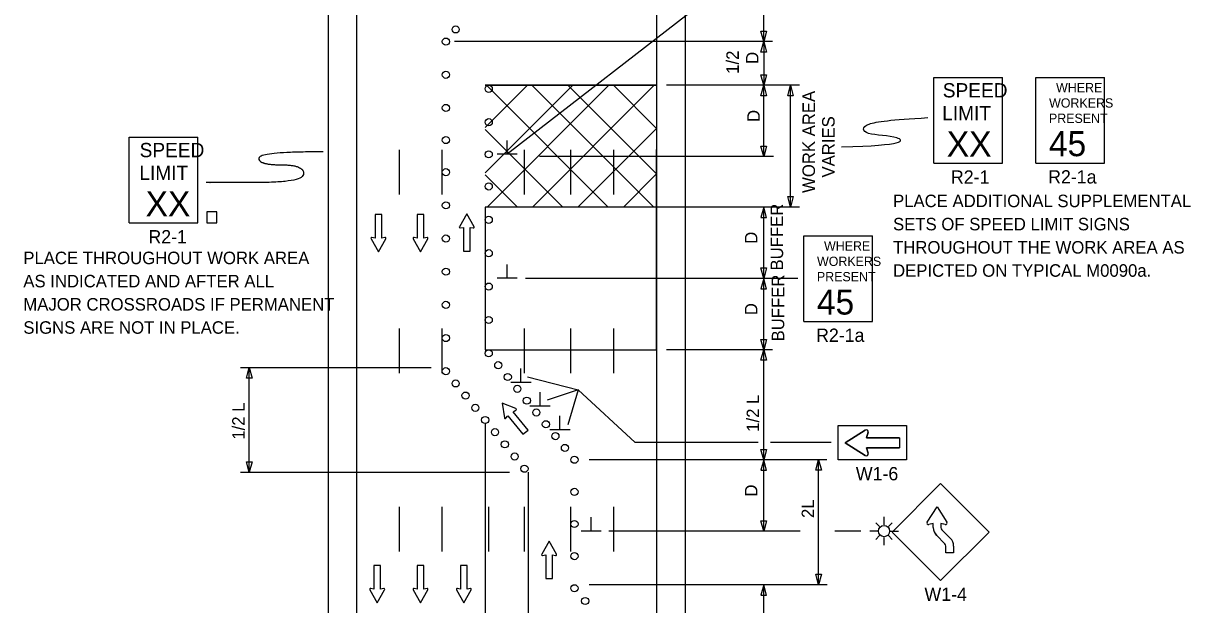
# Model space of a CAD drawing. Extents: x 16038 to 19504, y 5710 to 8321.
# Drawn here: x 16768 to 17422, y 6199 to 6525 of the extents above; entities that cross this region are included whole.
import ezdxf

# ---------------------------------------------------------------- set-up
doc = ezdxf.new("R2010")
doc.units = 0
for name, color, linetype in [('ALI_LEGAL_EX', 7, 'Continuous'), ('Level 3', 7, 'Continuous'), ('MT_SCRATCH_LEVEL_A', 7, 'Continuous'), ('MT_SCRATCH_LEVEL_E', 7, 'Continuous'), ('PAVT_EDGE_EX', 7, 'Continuous'), ('TRAFFIC_SIGNS_PR', 7, 'Continuous'), ('TYPICAL_EX', 7, 'Continuous'), ('TYPICAL_TEXT_DIMEN_PR', 7, 'Continuous')]:
    doc.layers.add(name, color=color, linetype=linetype)

msp = doc.modelspace()

# ---------------------------------------------------------------- linework, layer by layer
at = {"layer": 'ALI_LEGAL_EX'}
for points in [[(16978.71, 6429.12), (16978.71, 6454.12)], [(17002.71, 6429.12), (17002.71, 6454.12)], [(17048.71, 6429.12), (17048.71, 6454.12)], [(17074.71, 6429.12), (17074.71, 6454.12)], [(17098.71, 6429.12), (17098.71, 6454.12)], [(16978.71, 6329.12), (16978.71, 6354.12)], [(17002.71, 6329.12), (17002.71, 6354.12)], [(17048.71, 6329.12), (17048.71, 6354.12)], [(17074.71, 6329.12), (17074.71, 6354.12)], [(17098.71, 6329.12), (17098.71, 6354.12)], [(16978.71, 6229.12), (16978.71, 6254.12)], [(17002.71, 6229.12), (17002.71, 6254.12)], [(17028.71, 6229.12), (17028.71, 6254.12)], [(17048.71, 6229.12), (17048.71, 6254.12)], [(17074.71, 6229.12), (17074.71, 6254.12)], [(17098.71, 6229.12), (17098.71, 6254.12)]]:
    msp.add_lwpolyline(points, dxfattribs=at)
at = {"layer": 'Level 3'}
for p, q in [((17188.13, 6450.36), (17057.15, 6450.36)), ((17202.83, 6422.13), (17026.71, 6422.13)), ((17201.76, 6382.13), (17049.31, 6382.13)), ((17203.18, 6240.46), (17095.93, 6240.46)), ((17237.06, 6240.46), (17222.58, 6240.46))]:
    msp.add_line(p, q, dxfattribs=at)
at = {"layer": 'MT_SCRATCH_LEVEL_A'}
for p, q in [((17026.71, 6490.36), (17122.71, 6490.36)), ((17122.71, 6490.36), (17026.71, 6490.36)), ((17026.71, 6466.73), (17050.34, 6490.36)), ((17026.71, 6441.27), (17075.8, 6490.36)), ((17095.68, 6422.13), (17027.45, 6490.36)), ((17027.74, 6422.13), (17095.97, 6490.36)), ((17121.14, 6422.13), (17052.91, 6490.36)), ((17053.19, 6422.13), (17121.43, 6490.36)), ((17122.71, 6440.73), (17073.08, 6490.36)), ((17122.71, 6466.19), (17098.53, 6490.36)), ((17070.23, 6422.13), (17026.71, 6465.64)), ((17078.65, 6422.13), (17122.71, 6466.19)), ((17122.71, 6454.36), (17122.71, 6342.13)), ((17122.71, 6454.36), (17122.71, 6342.13)), ((17122.71, 6370.19), (17122.71, 6454.36)), ((17044.77, 6422.13), (17026.71, 6440.19)), ((17104.11, 6422.13), (17122.71, 6440.73)), ((17026.71, 6342.13), (17122.71, 6342.13)), ((17026.71, 6342.13), (17122.71, 6342.13))]:
    msp.add_line(p, q, dxfattribs=at)
at = {"layer": 'MT_SCRATCH_LEVEL_E'}
for p, q in [((16968.81, 6417.97), (16965.07, 6417.97)), ((16965.07, 6417.97), (16965.07, 6404.71)), ((16968.81, 6417.97), (16965.07, 6417.97)), ((16965.07, 6417.97), (16965.07, 6404.71)), ((16968.81, 6404.71), (16968.81, 6417.97)), ((16968.81, 6404.71), (16968.81, 6417.97)), ((16992.38, 6417.97), (16988.64, 6417.97)), ((16988.64, 6417.97), (16988.64, 6404.71)), ((16992.38, 6417.97), (16988.64, 6417.97)), ((16988.64, 6417.97), (16988.64, 6404.71)), ((16992.38, 6404.71), (16992.38, 6417.97)), ((16992.38, 6404.71), (16992.38, 6417.97)), ((17016.39, 6418.35), (17012.28, 6411.11)), ((17016.39, 6418.35), (17012.28, 6411.11)), ((17016.39, 6418.35), (17012.28, 6411.11)), ((17016.39, 6418.35), (17012.28, 6411.11)), ((17020.54, 6411.11), (17016.39, 6418.35)), ((17020.54, 6411.11), (17016.39, 6418.35)), ((17020.54, 6411.11), (17016.39, 6418.35)), ((17020.54, 6411.11), (17016.39, 6418.35)), ((17012.76, 6410.43), (17014.54, 6410.74)), ((17012.76, 6410.43), (17014.54, 6410.74)), ((17012.76, 6410.43), (17014.54, 6410.74)), ((17012.76, 6410.43), (17014.54, 6410.74)), ((17014.54, 6410.74), (17014.54, 6397.48)), ((17014.54, 6410.74), (17014.54, 6397.48)), ((17014.54, 6410.74), (17014.54, 6397.48)), ((17014.54, 6410.74), (17014.54, 6397.48)), ((17018.28, 6397.48), (17018.28, 6410.74)), ((17018.28, 6410.74), (17020.06, 6410.43)), ((17018.28, 6397.48), (17018.28, 6410.74)), ((17018.28, 6410.74), (17020.06, 6410.43)), ((17018.28, 6397.48), (17018.28, 6410.74)), ((17018.28, 6410.74), (17020.06, 6410.43)), ((17018.28, 6397.48), (17018.28, 6410.74)), ((17018.28, 6410.74), (17020.06, 6410.43)), ((16962.81, 6404.34), (16966.96, 6397.1)), ((16962.81, 6404.34), (16966.96, 6397.1)), ((16965.07, 6404.71), (16963.29, 6405.03)), ((16965.07, 6404.71), (16963.29, 6405.03)), ((16966.96, 6397.1), (16971.07, 6404.34)), ((16966.96, 6397.1), (16971.07, 6404.34)), ((16970.59, 6405.03), (16968.81, 6404.71)), ((16970.59, 6405.03), (16968.81, 6404.71)), ((16986.38, 6404.34), (16990.53, 6397.1)), ((16986.38, 6404.34), (16990.53, 6397.1)), ((16988.64, 6404.71), (16986.86, 6405.03)), ((16988.64, 6404.71), (16986.86, 6405.03)), ((16990.53, 6397.1), (16994.64, 6404.34)), ((16990.53, 6397.1), (16994.64, 6404.34)), ((16994.16, 6405.03), (16992.38, 6404.71)), ((16994.16, 6405.03), (16992.38, 6404.71)), ((17014.54, 6397.48), (17018.28, 6397.48)), ((17014.54, 6397.48), (17018.28, 6397.48)), ((17014.54, 6397.48), (17018.28, 6397.48)), ((17014.54, 6397.48), (17018.28, 6397.48)), ((17036.14, 6312.18), (17037.48, 6303.97)), ((17043.92, 6309.15), (17036.14, 6312.18)), ((17036.14, 6312.18), (17037.48, 6303.97)), ((17043.92, 6309.15), (17036.14, 6312.18)), ((17038.29, 6303.74), (17039.47, 6305.1)), ((17038.29, 6303.74), (17039.47, 6305.1)), ((17039.47, 6305.1), (17047.79, 6294.77)), ((17039.47, 6305.1), (17047.79, 6294.77)), ((17042.39, 6307.44), (17043.97, 6308.31)), ((17042.39, 6307.44), (17043.97, 6308.31)), ((17050.7, 6297.12), (17042.39, 6307.44)), ((17050.7, 6297.12), (17042.39, 6307.44)), ((17047.79, 6294.77), (17050.7, 6297.12)), ((17047.79, 6294.77), (17050.7, 6297.12)), ((17062.47, 6234.81), (17058.36, 6227.57)), ((17062.47, 6234.81), (17058.36, 6227.57)), ((17066.62, 6227.57), (17062.47, 6234.81)), ((17066.62, 6227.57), (17062.47, 6234.81)), ((17058.85, 6226.89), (17060.62, 6227.2)), ((17058.85, 6226.89), (17060.62, 6227.2)), ((17060.62, 6227.2), (17060.62, 6213.95)), ((17060.62, 6227.2), (17060.62, 6213.95)), ((17064.36, 6213.95), (17064.36, 6227.2)), ((17064.36, 6227.2), (17066.14, 6226.89)), ((17064.36, 6213.95), (17064.36, 6227.2)), ((17064.36, 6227.2), (17066.14, 6226.89)), ((16968.12, 6221.27), (16964.38, 6221.27)), ((16964.38, 6221.27), (16964.38, 6208.02)), ((16968.12, 6221.27), (16964.38, 6221.27)), ((16964.38, 6221.27), (16964.38, 6208.02)), ((16968.12, 6208.02), (16968.12, 6221.27)), ((16968.12, 6208.02), (16968.12, 6221.27)), ((16992.38, 6221.27), (16988.64, 6221.27)), ((16988.64, 6221.27), (16988.64, 6208.02)), ((16992.38, 6221.27), (16988.64, 6221.27)), ((16988.64, 6221.27), (16988.64, 6208.02)), ((16992.38, 6208.02), (16992.38, 6221.27)), ((16992.38, 6208.02), (16992.38, 6221.27)), ((17016.64, 6221.27), (17012.89, 6221.27)), ((17012.89, 6221.27), (17012.89, 6208.02)), ((17016.64, 6221.27), (17012.89, 6221.27)), ((17012.89, 6221.27), (17012.89, 6208.02)), ((17016.64, 6208.02), (17016.64, 6221.27)), ((17016.64, 6208.02), (17016.64, 6221.27)), ((17060.62, 6213.95), (17064.36, 6213.95)), ((17060.62, 6213.95), (17064.36, 6213.95)), ((16962.12, 6207.65), (16966.27, 6200.41)), ((16962.12, 6207.65), (16966.27, 6200.41)), ((16964.38, 6208.02), (16962.6, 6208.33)), ((16964.38, 6208.02), (16962.6, 6208.33)), ((16966.27, 6200.41), (16970.38, 6207.65)), ((16966.27, 6200.41), (16970.38, 6207.65)), ((16969.9, 6208.33), (16968.12, 6208.02)), ((16969.9, 6208.33), (16968.12, 6208.02)), ((16986.38, 6207.65), (16990.53, 6200.41)), ((16986.38, 6207.65), (16990.53, 6200.41)), ((16988.64, 6208.02), (16986.86, 6208.33)), ((16988.64, 6208.02), (16986.86, 6208.33)), ((16990.53, 6200.41), (16994.64, 6207.65)), ((16990.53, 6200.41), (16994.64, 6207.65)), ((16994.16, 6208.33), (16992.38, 6208.02)), ((16994.16, 6208.33), (16992.38, 6208.02)), ((17010.64, 6207.65), (17014.78, 6200.41)), ((17010.64, 6207.65), (17014.78, 6200.41)), ((17012.89, 6208.02), (17011.12, 6208.33)), ((17012.89, 6208.02), (17011.12, 6208.33)), ((17014.78, 6200.41), (17018.89, 6207.65)), ((17014.78, 6200.41), (17018.89, 6207.65)), ((17018.41, 6208.33), (17016.64, 6208.02)), ((17018.41, 6208.33), (17016.64, 6208.02))]:
    msp.add_line(p, q, dxfattribs=at)
for centre, start, end in [((17012.69, 6410.88), 150.42484, 279.96381), ((17012.69, 6410.88), 150.42484, 279.96381), ((17012.69, 6410.88), 150.42484, 279.96381), ((17012.69, 6410.88), 150.42484, 279.96381), ((17020.13, 6410.89), 260.03619, 29.77312), ((17020.13, 6410.89), 260.03619, 29.77312), ((17020.13, 6410.89), 260.03619, 29.77312), ((17020.13, 6410.89), 260.03619, 29.77312), ((16963.22, 6404.57), 80.03619, 209.77312), ((16963.22, 6404.57), 80.03619, 209.77312), ((16970.66, 6404.57), 330.42484, 99.96381), ((16970.66, 6404.57), 330.42484, 99.96381), ((16986.79, 6404.57), 80.03619, 209.77312), ((16986.79, 6404.57), 80.03619, 209.77312), ((16994.23, 6404.57), 330.42484, 99.96381), ((16994.23, 6404.57), 330.42484, 99.96381), ((17043.74, 6308.71), 298.87699, 68.61391), ((17043.74, 6308.71), 298.87699, 68.61391), ((17037.94, 6304.05), 189.26563, 318.8046), ((17037.94, 6304.05), 189.26563, 318.8046), ((17058.77, 6227.35), 150.42484, 279.96381), ((17058.77, 6227.35), 150.42484, 279.96381), ((17066.21, 6227.35), 260.03619, 29.77312), ((17066.21, 6227.35), 260.03619, 29.77312), ((16962.53, 6207.87), 80.03619, 209.77312), ((16962.53, 6207.87), 80.03619, 209.77312), ((16969.97, 6207.87), 330.42484, 99.96381), ((16969.97, 6207.87), 330.42484, 99.96381), ((16986.79, 6207.87), 80.03619, 209.77312), ((16986.79, 6207.87), 80.03619, 209.77312), ((16994.23, 6207.87), 330.42484, 99.96381), ((16994.23, 6207.87), 330.42484, 99.96381), ((17011.05, 6207.87), 80.03619, 209.77312), ((17011.05, 6207.87), 80.03619, 209.77312), ((17018.49, 6207.87), 330.42484, 99.96381), ((17018.49, 6207.87), 330.42484, 99.96381)]:
    msp.add_arc(centre, 0.463, start, end, dxfattribs=at)
at = {"layer": 'PAVT_EDGE_EX'}
for p, q in [((16954.71, 6925.32), (16954.71, 6077.44)), ((17122.71, 6925.32), (17122.71, 6077.44)), ((17138.71, 6925.32), (17138.71, 6077.44)), ((16938.71, 6780.67), (16938.71, 6077.44)), ((17026.71, 6300.81), (17026.71, 6077.44)), ((17050.71, 6273.49), (17050.71, 6077.44))]:
    msp.add_line(p, q, dxfattribs=at)
msp.add_lwpolyline([(17122.71, 6422.13), (17026.71, 6422.13), (17026.71, 6342.13), (17122.71, 6342.13)], close=True, dxfattribs=at)
at = {"layer": 'TRAFFIC_SIGNS_PR'}
for p, q in [((17277.94, 6494.67), (17316.34, 6494.67)), ((17277.94, 6446.67), (17277.94, 6494.67)), ((17316.34, 6446.67), (17316.34, 6494.67)), ((17335.13, 6494.76), (17373.53, 6494.76)), ((17335.13, 6446.76), (17335.13, 6494.76)), ((17373.53, 6446.76), (17373.53, 6494.76)), ((16827.43, 6461.19), (16865.83, 6461.19)), ((16827.43, 6413.19), (16827.43, 6461.19)), ((16865.83, 6413.19), (16865.83, 6461.19)), ((17277.94, 6446.67), (17316.34, 6446.67)), ((17335.13, 6446.76), (17373.53, 6446.76)), ((16827.43, 6413.19), (16865.83, 6413.19)), ((17205.17, 6406.02), (17243.57, 6406.02)), ((17205.17, 6358.02), (17205.17, 6406.02)), ((17243.57, 6358.02), (17243.57, 6406.02)), ((17205.17, 6358.02), (17243.57, 6358.02)), ((17239.51, 6297.14), (17228.35, 6290.03)), ((17240.35, 6292.84), (17241.19, 6295.9)), ((17228.35, 6290.03), (17239.51, 6282.93)), ((17258.75, 6292.84), (17240.35, 6292.84)), ((17258.75, 6292.84), (17258.75, 6287.24)), ((17241.19, 6284.18), (17240.35, 6287.24)), ((17240.35, 6287.24), (17258.75, 6287.24)), ((17254.58, 6239.99), (17281.73, 6267.14)), ((17308.88, 6239.99), (17281.73, 6267.14)), ((17247.58, 6243.04), (17245.47, 6245.15)), ((17250.09, 6244.08), (17250.09, 6248.58)), ((17252.61, 6243.04), (17254.71, 6245.15)), ((17246.94, 6240.53), (17242.1, 6240.53)), ((17247.58, 6238.01), (17245.47, 6235.9)), ((17250.09, 6232.56), (17250.09, 6236.97)), ((17252.61, 6238.01), (17254.71, 6235.91)), ((17253.25, 6240.53), (17258.13, 6240.53)), ((17281.73, 6212.84), (17254.58, 6239.99)), ((17284.15, 6233.47), (17279.44, 6238.19)), ((17284.15, 6233.47), (17279.44, 6238.19)), ((17308.88, 6239.99), (17281.73, 6212.84)), ((17287.2, 6236.52), (17282.49, 6241.24)), ((17282.49, 6241.24), (17287.2, 6236.52))]:
    msp.add_line(p, q, dxfattribs=at)
for points in [[(16870.85, 6413.19), (16876.44, 6413.19), (16876.44, 6419.36), (16870.85, 6419.36)], [(17262.75, 6280.44), (17224.35, 6280.44), (17224.35, 6299.64), (17262.75, 6299.64)]]:
    msp.add_lwpolyline(points, close=True, dxfattribs=at)
for points in [[(17239.51, 6282.93), (17228.35, 6290.03), (17239.51, 6297.14)], [(17241.19, 6295.9), (17240.35, 6292.84), (17258.75, 6292.84), (17258.75, 6287.24), (17240.35, 6287.24), (17241.19, 6284.18)], [(17274.28, 6245.51), (17279.76, 6254.12), (17285.25, 6245.51)], [(17274.28, 6245.51), (17279.76, 6254.12), (17285.25, 6245.51)], [(17277.61, 6242.5), (17277.61, 6244.86), (17275.24, 6244.21)], [(17277.61, 6242.5), (17277.61, 6244.86), (17275.24, 6244.21)], [(17284.29, 6244.21), (17281.92, 6244.86), (17281.93, 6242.57)], [(17284.29, 6244.21), (17283.45, 6244.44), (17281.92, 6244.86), (17281.93, 6242.57)], [(17289.07, 6232.1), (17289.07, 6228.4), (17284.75, 6228.4), (17284.75, 6232.1)]]:
    msp.add_lwpolyline(points, dxfattribs=at)
for centre, radius in [((17010.21, 6521.65), 2), ((17004.71, 6514.82), 2), ((17004.71, 6514.82), 2), ((17004.71, 6496.23), 2), ((17028.71, 6488.36), 2), ((17004.71, 6477.65), 2), ((17028.71, 6469.65), 2), ((17004.71, 6459.65), 2), ((17028.71, 6451.65), 2), ((17004.71, 6441.65), 2), ((17028.71, 6433.65), 2), ((17004.71, 6423.06), 2), ((17028.71, 6414.95), 2), ((17004.71, 6404.47), 2), ((17028.71, 6396.24), 2), ((17004.71, 6385.89), 2), ((17028.71, 6377.54), 2), ((17004.71, 6367.3), 2), ((17028.71, 6358.83), 2), ((17004.71, 6348.71), 2), ((17028.71, 6340.13), 2), ((17034.04, 6333.5), 2), ((17004.71, 6330.13), 2), ((17039.38, 6326.88), 2), ((17010.21, 6323.3), 2), ((17044.71, 6320.26), 2), ((17015.71, 6316.47), 2), ((17050.04, 6313.63), 2), ((17021.21, 6309.64), 2), ((17055.38, 6307.01), 2), ((17026.71, 6302.81), 2), ((17060.71, 6300.39), 2), ((17032.21, 6295.98), 2), ((17066.04, 6293.76), 2), ((17037.71, 6289.15), 2), ((17071.38, 6287.14), 2), ((17043.21, 6282.32), 2), ((17076.71, 6280.51), 2), ((17048.71, 6275.49), 2), ((17076.71, 6262.51), 2), ((17076.71, 6244.51), 2), ((17250.09, 6240.53), 3.15), ((17076.71, 6226.51), 2), ((17076.71, 6208.51), 2), ((17076.71, 6208.51), 2), ((17082.71, 6201.37), 2)]:
    msp.add_circle(centre, radius, dxfattribs=at)
for centre, radius, start, end in [((17240.11, 6296.19), 1.12, 344.67308, 122.46963), ((17240.11, 6296.19), 1.12, 344.67308, 122.46962), ((17240.11, 6283.88), 1.12, 237.53038, 15.32692), ((17240.11, 6283.88), 1.12, 237.53038, 15.32692), ((17275.01, 6245.05), 0.866, 147.7292, 285.31719), ((17275.01, 6245.05), 0.866, 147.71964, 285.32011), ((17265.17, 6251.31), 10.8, 327.53351, 327.54311), ((17278.1, 6233.79), 10.8, 105.31922, 105.32004), ((17284.52, 6245.05), 0.866, 254.61481, 32.47119), ((17283.78, 6242.56), 6.17, 180.61811, 225.78746), ((17283.78, 6242.56), 6.17, 180.62445, 225.23128), ((17283.78, 6242.56), 1.85, 179.8762, 225.7877), ((17283.78, 6242.56), 1.85, 180, 225.78746), ((17282.9, 6232.1), 1.85, 0, 47.62801), ((17282.9, 6232.1), 6.17, 0, 45.78828)]:
    msp.add_arc(centre, radius, start, end, dxfattribs=at)
at = {"layer": 'TYPICAL_EX'}
msp.add_line((16938.71, 6925.32), (16938.71, 6077.44), dxfattribs=at)
at = {"layer": 'TYPICAL_TEXT_DIMEN_PR'}
for p, q in [((17182.71, 6514.82), (17182.71, 6571.46)), ((17166.55, 6550.67), (17039.04, 6451.72)), ((17182.71, 6514.82), (17181.14, 6520.68)), ((17181.14, 6520.68), (17182.71, 6520.68)), ((17182.71, 6520.68), (17184.28, 6520.68)), ((17184.28, 6520.68), (17182.71, 6514.82)), ((17187.71, 6514.82), (17009.59, 6514.82)), ((17181.14, 6508.96), (17182.71, 6514.82)), ((17182.71, 6514.82), (17184.28, 6508.96)), ((17182.71, 6514.82), (17182.71, 6490.36)), ((17182.71, 6508.96), (17181.14, 6508.96)), ((17184.28, 6508.96), (17182.71, 6508.96)), ((17182.71, 6490.36), (17181.14, 6496.22)), ((17181.14, 6496.22), (17182.71, 6496.22)), ((17182.71, 6496.22), (17184.28, 6496.22)), ((17184.28, 6496.22), (17182.71, 6490.36)), ((17202.83, 6490.36), (17128.21, 6490.36)), ((17181.14, 6484.5), (17182.71, 6490.36)), ((17182.71, 6450.36), (17182.71, 6490.36)), ((17182.71, 6490.36), (17184.28, 6484.5)), ((17196.14, 6484.5), (17197.71, 6490.36)), ((17197.71, 6422.13), (17197.71, 6490.36)), ((17197.71, 6490.36), (17199.28, 6484.5)), ((17182.71, 6484.5), (17181.14, 6484.5)), ((17184.28, 6484.5), (17182.71, 6484.5)), ((17197.71, 6484.5), (17196.14, 6484.5)), ((17199.28, 6484.5), (17197.71, 6484.5)), ((17039.04, 6451.72), (17039.04, 6459.5)), ((17182.71, 6450.36), (17181.14, 6456.22)), ((17181.14, 6456.22), (17182.71, 6456.22)), ((17182.71, 6456.22), (17184.28, 6456.22)), ((17184.28, 6456.22), (17182.71, 6450.36)), ((17044.66, 6451.72), (17033.41, 6451.72)), ((17197.71, 6422.13), (17196.14, 6427.99)), ((17196.14, 6427.99), (17197.71, 6427.99)), ((17197.71, 6427.99), (17199.28, 6427.99)), ((17199.28, 6427.99), (17197.71, 6422.13)), ((17182.71, 6422.13), (17181.14, 6416.27)), ((17182.71, 6382.13), (17182.71, 6422.13)), ((17184.28, 6416.27), (17182.71, 6422.13)), ((17181.14, 6416.27), (17182.71, 6416.27)), ((17182.71, 6416.27), (17184.28, 6416.27)), ((17039.04, 6382.22), (17039.04, 6390.01)), ((17182.71, 6382.13), (17181.14, 6387.99)), ((17181.14, 6387.99), (17182.71, 6387.99)), ((17182.71, 6387.99), (17184.28, 6387.99)), ((17184.28, 6387.99), (17182.71, 6382.13)), ((17044.66, 6382.22), (17033.41, 6382.22)), ((17182.71, 6382.13), (17181.14, 6376.27)), ((17182.71, 6342.13), (17182.71, 6382.13)), ((17184.28, 6376.27), (17182.71, 6382.13)), ((17181.14, 6376.27), (17182.71, 6376.27)), ((17182.71, 6376.27), (17184.28, 6376.27)), ((17182.71, 6342.13), (17181.14, 6347.99)), ((17181.14, 6347.99), (17182.71, 6347.99)), ((17182.71, 6347.99), (17184.28, 6347.99)), ((17184.28, 6347.99), (17182.71, 6342.13)), ((17187.71, 6342.13), (17128.21, 6342.13)), ((17181.14, 6336.27), (17182.71, 6342.13)), ((17182.71, 6342.13), (17184.28, 6336.27)), ((17182.71, 6280.46), (17182.71, 6342.13)), ((17182.71, 6336.27), (17181.14, 6336.27)), ((17184.28, 6336.27), (17182.71, 6336.27)), ((16889.61, 6332.13), (16996.39, 6332.13)), ((16893.04, 6326.27), (16894.61, 6332.13)), ((16894.61, 6273.48), (16894.61, 6332.13)), ((16894.61, 6332.13), (16896.18, 6326.27)), ((17046.76, 6323.82), (17046.76, 6331.61)), ((16894.61, 6326.27), (16893.04, 6326.27)), ((16896.18, 6326.27), (16894.61, 6326.27)), ((17052.38, 6323.82), (17041.13, 6323.82)), ((17050.46, 6327.06), (17078.72, 6319.64)), ((17057.42, 6310.61), (17057.42, 6318.39)), ((17078.72, 6319.64), (17061.46, 6313.94)), ((17078.72, 6319.64), (17073.03, 6300.05)), ((17078.72, 6319.64), (17110.7, 6290.12)), ((17063.05, 6310.61), (17051.8, 6310.61)), ((17068.59, 6297.28), (17068.59, 6305.07)), ((17074.22, 6297.28), (17062.97, 6297.28)), ((17179.54, 6290.12), (17110.7, 6290.12)), ((17220.43, 6290.12), (17186.53, 6290.12)), ((17182.71, 6280.46), (17181.14, 6286.33)), ((17181.14, 6286.33), (17182.71, 6286.33)), ((17182.71, 6286.33), (17184.28, 6286.33)), ((17184.28, 6286.33), (17182.71, 6280.46)), ((16894.61, 6273.48), (16893.04, 6279.35)), ((16893.04, 6279.35), (16894.61, 6279.35)), ((16894.61, 6279.35), (16896.18, 6279.35)), ((16896.18, 6279.35), (16894.61, 6273.48)), ((17217.96, 6280.46), (17084.95, 6280.46)), ((17182.71, 6280.46), (17181.14, 6274.6)), ((17182.71, 6240.46), (17182.71, 6280.46)), ((17184.28, 6274.6), (17182.71, 6280.46)), ((17211.85, 6274.6), (17213.42, 6280.46)), ((17213.42, 6210.46), (17213.42, 6280.46)), ((17213.42, 6280.46), (17214.99, 6274.6)), ((16889.61, 6273.48), (17040.43, 6273.48)), ((17181.14, 6274.6), (17182.71, 6274.6)), ((17182.71, 6274.6), (17184.28, 6274.6)), ((17213.42, 6274.6), (17211.85, 6274.6)), ((17214.99, 6274.6), (17213.42, 6274.6)), ((17086.07, 6240.54), (17086.07, 6248.33)), ((17182.71, 6240.46), (17181.14, 6246.33)), ((17181.14, 6246.33), (17182.71, 6246.33)), ((17182.71, 6246.33), (17184.28, 6246.33)), ((17184.28, 6246.33), (17182.71, 6240.46)), ((17091.7, 6240.54), (17080.45, 6240.54)), ((17218.29, 6210.46), (17084.95, 6210.46)), ((17182.71, 6210.46), (17181.14, 6204.6)), ((17182.71, 6179.95), (17182.71, 6210.46)), ((17184.28, 6204.6), (17182.71, 6210.46)), ((17213.42, 6210.46), (17211.85, 6216.32)), ((17211.85, 6216.32), (17213.42, 6216.32)), ((17213.42, 6216.32), (17214.99, 6216.32)), ((17214.99, 6216.32), (17213.42, 6210.46)), ((17181.14, 6204.6), (17182.71, 6204.6)), ((17182.71, 6204.6), (17184.28, 6204.6))]:
    msp.add_line(p, q, dxfattribs=at)
for points, degree in [([(17226.21, 6455.77), (17262.51, 6456.7), (17260.65, 6462.24), (17237.6, 6462.24), (17237.6, 6469.34), (17254, 6470.95), (17274.53, 6472.25)], 3), ([(16935.98, 6453.06), (16899.89, 6453.06), (16899.89, 6445.8), (16925.07, 6445.8), (16925.07, 6435.89), (16875.42, 6435.89), (16870.49, 6435.89)], 2)]:
    msp.add_open_spline(points, degree=degree, dxfattribs=at)

# ---------------------------------------------------------------- texts
at = {"layer": 'TRAFFIC_SIGNS_PR'}
for s, height, p in [('SPEED', 8, (17282.97, 6483.54)), ('WHERE', 5.2, (17346.44, 6486.45)), ('LIMIT', 8, (17282.64, 6470.74)), ('WORKERS', 5.2, (17342.52, 6477.85)), ('PRESENT', 5.2, (17342.45, 6469.25)), ('XX', 14.031, (17285.24, 6450.43)), ('45', 14.031, (17342.44, 6450.62)), ('SPEED', 8, (16833.2, 6450.06)), ('LIMIT', 8, (16833.04, 6437.26)), ('R2-1', 7.44, (17287.55, 6435.23)), ('R2-1a', 7.44, (17341.99, 6435.32)), ('XX', 14.031, (16836.54, 6416.95)), ('PLACE ADDITIONAL SUPPLEMENTAL', 7, (17255.13, 6422.06)), ('SETS OF SPEED LIMIT SIGNS', 7, (17255.13, 6409.06)), ('R2-1', 7.44, (16838.11, 6401.75)), ('WHERE', 5.2, (17216.48, 6397.71)), ('THROUGHOUT THE WORK AREA AS', 7, (17255.13, 6396.06)), ('PLACE THROUGHOUT WORK AREA', 7, (16768.06, 6390.12)), ('WORKERS', 5.2, (17212.56, 6389.11)), ('DEPICTED ON TYPICAL M0090a.', 7, (17255.13, 6383.06)), ('AS INDICATED AND AFTER ALL', 7, (16768.06, 6377.12)), ('PRESENT', 5.2, (17212.49, 6380.51)), ('45', 14.031, (17212.48, 6361.88)), ('MAJOR CROSSROADS IF PERMANENT', 7, (16768.06, 6364.12)), ('SIGNS ARE NOT IN PLACE.', 7, (16768.06, 6351.12)), ('R2-1a', 7.44, (17212.03, 6346.58)), ('W1-6', 7.44, (17234.29, 6268.99)), ('W1-4', 7.44, (17272.73, 6201.4))]:
    msp.add_text(s, height=height, dxfattribs=at).set_placement(p)
at = {"layer": 'TYPICAL_TEXT_DIMEN_PR'}
for s, p in [('1/2', (17168.78, 6496.78)), ('D', (17179.78, 6502.35)), ('WORK AREA', (17211.42, 6430.03)), ('D', (17180.53, 6469.8)), ('VARIES', (17222.42, 6438.67)), ('BUFFER', (17193.59, 6386.57)), ('D', (17179.14, 6401.53)), ('BUFFER', (17194.2, 6346.82)), ('D', (17179.14, 6361.53)), ('1/2 L', (17180.15, 6296.18)), ('1/2 L', (16892.05, 6291.78)), ('D', (17179.14, 6259.87)), ('2L', (17210.93, 6247.86))]:
    msp.add_text(s, height=7, rotation=90, dxfattribs=at).set_placement(p)

doc.saveas('drawing.dxf')
